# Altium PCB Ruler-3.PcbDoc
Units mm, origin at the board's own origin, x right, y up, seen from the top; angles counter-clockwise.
Board outline 100.08 x 35.05 mm, 2 copper layers (Top Layer, Bottom Layer); 12 components, 0 nets, 672 pads, 0 vias.
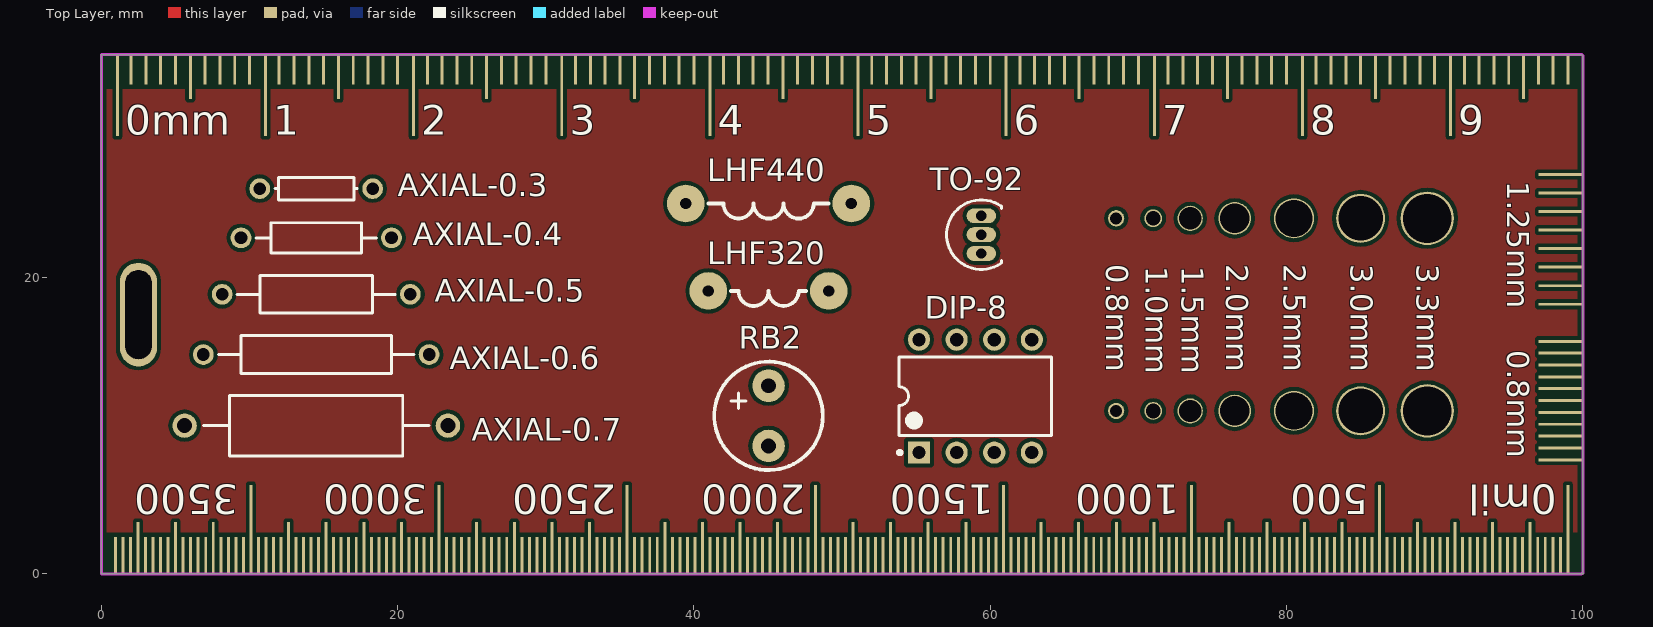
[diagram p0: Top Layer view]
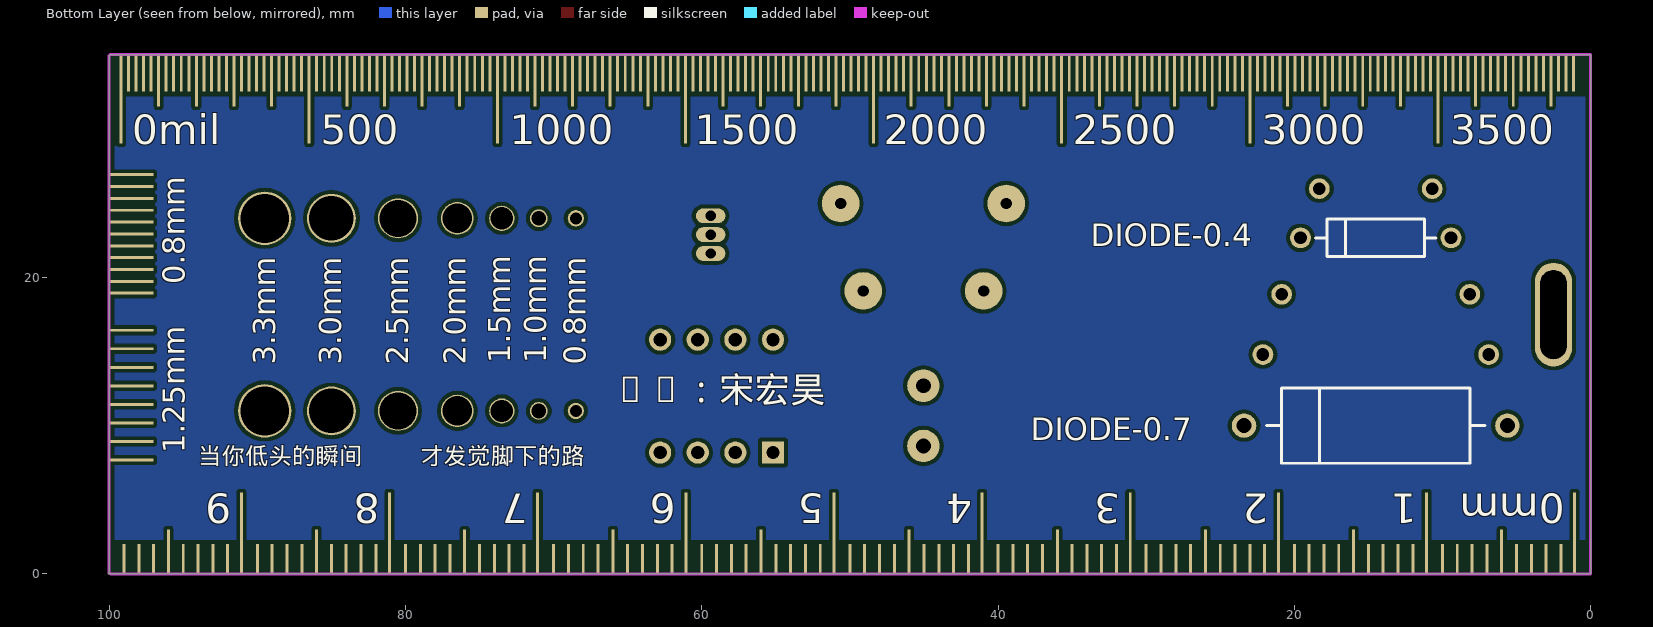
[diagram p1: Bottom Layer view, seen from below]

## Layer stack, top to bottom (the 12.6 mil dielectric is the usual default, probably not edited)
Top Solder: solder mask 0.0102, Solder Resist, Dk 3.5
Top Layer: signal copper 0.0356
Dielectric 1: dielectric 0.32, FR-4, Dk 4.8
Bottom Layer: signal copper 0.0356
Bottom Solder: solder mask 0.0102, Solder Resist, Dk 3.5

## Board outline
0,0 0,35.052 99.948,35.052 100,35 100,0.076 100.076,0

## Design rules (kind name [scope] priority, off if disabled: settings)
Clearance Clearance_1 [InPolygon] p1: gap=0.254 ignorepadtopadclearanceinfootprint=FALSE
Clearance [All] p2: gap=0.254 ignorepadtopadclearanceinfootprint=FALSE except(0: Arc-Hole Track-Hole SMDPad-Hole THPad-Hole Via-Hole Fill-Hole Poly-Hole Region-Hole Text-Hole)
PolygonConnect [All] p1: connectstyle=Relief reliefconductorwidth=0.254 reliefentries=4 polygonreliefangle="90 Angle" airgapwidth=0.254
RoutingVias [All] p1: holewidth=0.711 width=1.27 viastyle="Through Hole" minholewidth=0.711 minwidth=1.27 maxholewidth=0.711 maxwidth=1.27
SolderMaskExpansion [All] p1: expansion=0.102
Width [All] p1: maxlimit=0.254 minlimit=0.254 preferedwidth=0.254
30 further rules are at their usual default settings.

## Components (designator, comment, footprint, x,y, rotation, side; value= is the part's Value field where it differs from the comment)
AXIAL-0.3 "AXIAL-0.3" AXIAL-0.3 14.5,26 r0 top
AXIAL-0.4 "AXIAL-0.4" AXIAL-0.4 14.5,22.686 r0 top
AXIAL-0.5 "AXIAL-0.5" AXIAL-0.5 14.5,18.873 r0 top
AXIAL-0.6 "AXIAL-0.6" AXIAL-0.6 14.5,14.805 r0 top
AXIAL-0.7 "AXIAL-0.7" AXIAL-0.7 14.5,10 r0 top
DIODE-0.4 "DIODE-0.4" DIODE-0.4 14.503,22.682 r0 bottom
DIODE-0.7 "DIODE-0.7" DIODE-0.7 14.503,10.008 r0 bottom
DIP-8 "DIP-8" DIP-8 59,12 r90 top
LHF320 "LHF320" LHF320 49.1,19.1 r180 top
LHF440 "LHF440" LHF440 50.624,25 r180 top
RB2 "RB2" RB2 44.528,12.7 r90 top
TO-92 "TO-92" TO-92 59.399,22.9 r0 top

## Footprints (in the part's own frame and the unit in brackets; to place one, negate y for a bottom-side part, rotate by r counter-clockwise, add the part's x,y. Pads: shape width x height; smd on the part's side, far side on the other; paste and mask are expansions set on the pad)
AXIAL-0.3 [mm] "Axial Device, Thru-Hole; 2 Leads; 0.3 in Pin Spacing"
  round 1.4 hole 0.85: 1(-3.81,0) 2(3.81,0)
  silkscreen extent -2.77,-0.76 2.77,0.76
AXIAL-0.4 [mm] "Axial Device, Thru-Hole; 2 Leads; 0.4 in Pin Spacing"
  round 1.4 hole 0.85: 1(-5.08,0) 2(5.08,0)
  silkscreen extent -4.06,-1.02 4.06,1.02
AXIAL-0.5 [mm] "Axial Device, Thru-Hole; 2 Leads; 0.5 in Pin Spacing"
  round 1.4 hole 0.85: 1(-6.35,0) 2(6.35,0)
  silkscreen extent -5.33,-1.27 5.33,1.27
AXIAL-0.6 [mm] "Axial Device, Thru-Hole; 2 Leads; 0.6 in Pin Spacing"
  round 1.4 hole 0.85: 1(-7.62,0) 2(7.62,0)
  silkscreen extent -6.6,-1.27 6.6,1.27
AXIAL-0.7 [mm] "Axial Device, Thru-Hole; 2 Leads; 0.7 in Pin Spacing"
  round 1.4 hole 0.85: 1(-8.89,0) 2(8.89,0)
  silkscreen extent -7.62,-2.03 7.62,2.03
DIODE-0.4 [mm] "Diode, Thru-Hole; 2 Leads; 0.4 in Pin Spacing"
  round 1.4 hole 0.85: 1(-5.08,0) 2(5.08,0)
  silkscreen extent -4.06,-1.27 4.06,1.27
DIODE-0.7 [mm] "Diode, Thru-Hole; 2 Leads; 0.7 in Pin Spacing"
  round 1.65 hole 1: 1(-8.89,0) 2(8.89,0)
  silkscreen extent -7.37,-2.54 7.37,2.54
DIP-8 [mm] "DIP; 8 Leads; Row Spacing 7.62 mm; Pitch 2.54 mm"
  rect 1.5x1.5 hole 0.9: 1(-3.81,3.81)
  round 1.5 hole 0.9: 2(-3.81,1.27) 3(-3.81,-1.27) 4(-3.81,-3.81) 5(3.81,-3.81) 6(3.81,-1.27) 7(3.81,1.27) 8(3.81,3.81)
  silkscreen extent -3.93,-5.15 2.65,5.23, body extent -3.6,-5.15 3.6,5.15, height 5.08
LHF320 [mil]
  round 100 hole 30: 1(0,0) 2(320,0)
  silkscreen extent 60,0 260,40
LHF440 [mil]
  round 100 hole 30: 1(0,0) 2(440,0)
  silkscreen extent 60,0 380,40
RB2 [mm]
  round 2.2 hole 1: 1(0,-0.508) 2(-4.064,-0.508)
  silkscreen extent -5.69,-4.17 1.63,3.15
TO-92 [mm] "TO, Flat Index; 3 In-Line, Axial Leads; Body Dia. 4.6mm; Leads 0.41 x 0.39 mm (max)"
  oval 2x1 hole 0.7: 1(0,1.27) 2(0,0) 3(0,-1.27)
  silkscreen extent -2.34,-2.34 1.35,2.34

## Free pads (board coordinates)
  oval 2.5x7 hole 1.8 slot 6 at 90 deg: 0(2.5,17.5)
  rect 0.2x5.5 smd far side: 1(1.075,2.752) 11(11.075,2.752) 21(21.075,2.752) 31(31.075,2.752) 41(41.075,2.752) 51(51.075,2.752) 61(61.075,2.752) 71(71.075,2.752) 81(81.075,2.752) 91(91.075,2.752)
  rect 0.2x5.5 smd: 1(1.075,32.3) 11(11.075,32.3) 21(21.075,32.3) 31(31.075,32.3) 41(41.075,32.3) 51(51.075,32.3) 61(61.075,32.3) 71(71.075,32.3) 81(81.075,32.3) 91(91.075,32.3)
  round 3.3 hole 3: 1(85,24) 2(85,11)
  rect 0.2x2 smd far side: 2(2,1.002) 3(3,1.002) 4(4,1.002) 5(5,1.002) 7(7,1.002) 8(8,1.002) 9(9,1.002) 10(10,1.002) 12(12,1.002) 13(13,1.002) 14(14,1.002) 15(15,1.002) 17(17,1.002) 18(18,1.002) 19(19,1.002) 20(20,1.002) 22(22,1.002) 23(23,1.002) 24(24,1.002) 25(25,1.002) 27(27,1.002) 28(28,1.002) 29(29,1.002) 30(30,1.002) 32(32,1.002) 33(33,1.002) 34(34,1.002) 35(35,1.002) 37(37,1.002) 38(38,1.002) 39(39,1.002) 40(40,1.002) 42(42,1.002) 43(43,1.002) 44(44,1.002) 45(45,1.002) 47(47,1.002) 48(48,1.002) 49(49,1.002) 50(50,1.002) 52(52,1.002) 53(53,1.002) 54(54,1.002) 55(55,1.002) 57(57,1.002) 58(58,1.002) 59(59,1.002) 60(60,1.002) 62(62,1.002) 63(63,1.002) 64(64,1.002) 65(65,1.002) 67(67,1.002) 68(68,1.002) 69(69,1.002) 70(70,1.002) 72(72,1.002) 73(73,1.002) 74(74,1.002) 75(75,1.002) 77(77,1.002) 78(78,1.002) 79(79,1.002) 80(80,1.002) 82(82,1.002) 83(83,1.002) 84(84,1.002) 85(85,1.002) 87(87,1.002) 88(88,1.002) 89(89,1.002) 90(90,1.002) 92(92,1.002) 93(92,1.002) 94(93,1.002) 95(94,1.002) 96(95,1.002) 98(97,1.002) 99(98,1.002) 100(99,1.002)
  rect 0.2x2 smd: 2(2,34.05) 3(3,34.05) 4(4,34.05) 5(5,34.05) 7(7,34.05) 8(8,34.05) 9(9,34.05) 10(10,34.05) 12(12,34.05) 13(13,34.05) 14(14,34.05) 15(15,34.05) 17(17,34.05) 18(18,34.05) 19(19,34.05) 20(20,34.05) 22(22,34.05) 23(23,34.05) 24(24,34.05) 25(25,34.05) 27(27,34.05) 28(28,34.05) 29(29,34.05) 30(30,34.05) 32(32,34.05) 33(33,34.05) 34(34,34.05) 35(35,34.05) 37(37,34.05) 38(38,34.05) 39(39,34.05) 40(40,34.05) 42(42,34.05) 43(43,34.05) 44(44,34.05) 45(45,34.05) 47(47,34.05) 48(48,34.05) 49(49,34.05) 50(50,34.05) 52(52,34.05) 53(53,34.05) 54(54,34.05) 55(55,34.05) 57(57,34.05) 58(58,34.05) 59(59,34.05) 60(60,34.05) 62(62,34.05) 63(63,34.05) 64(64,34.05) 65(65,34.05) 67(67,34.05) 68(68,34.05) 69(69,34.05) 70(70,34.05) 72(72,34.05) 73(73,34.05) 74(74,34.05) 75(75,34.05) 77(77,34.05) 78(78,34.05) 79(79,34.05) 80(80,34.05) 82(82,34.05) 83(83,34.05) 84(84,34.05) 85(85,34.05) 87(87,34.05) 88(88,34.05) 89(89,34.05) 90(90,34.05) 92(92,34.05) 93(92,34.05) 94(93,34.05) 95(94,34.05) 96(95,34.05) 98(97,34.05) 99(98,34.05) 100(99,34.05)
  rect 0.2x3 smd far side: 6(6,1.502) 16(16,1.502) 26(26,1.502) 36(36,1.502) 46(46,1.502) 56(56,1.502) 66(66,1.502) 76(76,1.502) 86(86,1.502) 97(96,1.502)
  rect 0.2x3 smd: 6(6,33.55) 16(16,33.55) 26(26,33.55) 36(36,33.55) 46(46,33.55) 56(56,33.55) 66(66,33.55) 76(76,33.55) 86(86,33.55) 97(96,33.55)
  rect 0.2x6 smd: 102(98.99,3.002) 129(86.29,3.002) 154(73.59,3.002) 179(60.89,3.002) 204(48.19,3.002) 229(35.49,3.002) 254(22.79,3.002) 279(10.09,3.002)
  rect 0.2x6 smd far side: 102(99.2,32.05) 129(86.5,32.05) 154(73.8,32.05) 179(61.1,32.05) 204(48.4,32.05) 229(35.7,32.05) 254(23,32.05) 279(10.3,32.05)
  rect 0.2x2.5 smd: 103(98.482,1.252) 104(97.974,1.252) 107(97.466,1.252) 108(96.958,1.252) 110(95.942,1.252) 111(95.434,1.252) 112(94.926,1.252) 113(94.418,1.252) 115(93.402,1.252) 116(92.894,1.252) 117(92.386,1.252) 118(91.878,1.252) 120(90.862,1.252) 121(90.354,1.252) 122(89.846,1.252) 123(89.338,1.252) 125(88.322,1.252) 126(87.814,1.252) 127(87.306,1.252) 128(86.798,1.252) 130(85.782,1.252) 131(85.274,1.252) 132(84.766,1.252) 133(84.258,1.252) 135(83.242,1.252) 136(82.734,1.252) 137(82.226,1.252) 138(81.718,1.252) 140(80.702,1.252) 141(80.194,1.252) 142(79.686,1.252) 143(79.178,1.252) 145(78.162,1.252) 146(77.654,1.252) 147(77.146,1.252) 148(76.638,1.252) 150(75.622,1.252) 151(75.114,1.252) 152(74.606,1.252) 153(74.098,1.252) 155(73.082,1.252) 156(72.574,1.252) 157(72.066,1.252) 158(71.558,1.252) 160(70.542,1.252) 161(70.034,1.252) 162(69.526,1.252) 163(69.018,1.252) 165(68.002,1.252) 166(67.494,1.252) 167(66.986,1.252) 168(66.478,1.252) 170(65.462,1.252) 171(64.954,1.252) 172(64.446,1.252) 173(63.938,1.252) 175(62.922,1.252) 176(62.414,1.252) 177(61.906,1.252) 178(61.398,1.252) 180(60.382,1.252) 181(59.874,1.252) 182(59.366,1.252) 183(58.858,1.252) 185(57.842,1.252) 186(57.334,1.252) 187(56.826,1.252) 188(56.318,1.252) 190(55.302,1.252) 191(54.794,1.252) 192(54.286,1.252) 193(53.778,1.252) 195(52.762,1.252) 196(52.254,1.252) 197(51.746,1.252) 198(51.238,1.252) 200(50.222,1.252) 201(49.714,1.252) 202(49.206,1.252) 203(48.698,1.252) 205(47.682,1.252) 206(47.174,1.252) 207(46.666,1.252) 208(46.158,1.252) 210(45.142,1.252) 211(44.634,1.252) 212(44.126,1.252) 213(43.618,1.252) 215(42.602,1.252) 216(42.094,1.252) 217(41.586,1.252) 218(41.078,1.252) 220(40.062,1.252) 221(39.554,1.252) 222(39.046,1.252) 223(38.538,1.252) 225(37.522,1.252) 226(37.014,1.252) 227(36.506,1.252) 228(35.998,1.252) 230(34.982,1.252) 231(34.474,1.252) 232(33.966,1.252) 233(33.458,1.252) 235(32.442,1.252) 236(31.934,1.252) 237(31.426,1.252) 238(30.918,1.252) 240(29.902,1.252) 241(29.394,1.252) 242(28.886,1.252) 243(28.378,1.252) 245(27.362,1.252) 246(26.854,1.252) 247(26.346,1.252) 248(25.838,1.252) 250(24.822,1.252) 251(24.314,1.252) 252(23.806,1.252) 253(23.298,1.252) 255(22.282,1.252) 256(21.774,1.252) 257(21.266,1.252) 258(20.758,1.252) 260(19.742,1.252) 261(19.234,1.252) 262(18.726,1.252) 263(18.218,1.252) 265(17.202,1.252) 266(16.694,1.252) 267(16.186,1.252) 268(15.678,1.252) 270(14.662,1.252) 271(14.154,1.252) 272(13.646,1.252) 273(13.138,1.252) 275(12.122,1.252) 276(11.614,1.252) 277(11.106,1.252) 278(10.598,1.252) 280(9.582,1.252) 281(9.074,1.252) 282(8.566,1.252) 283(8.058,1.252) 285(7.042,1.252) 286(6.534,1.252) 287(6.026,1.252) 288(5.518,1.252) 290(4.502,1.252) 291(3.994,1.252) 292(3.486,1.252) 293(2.978,1.252) 295(1.962,1.252) 296(1.454,1.252) 297(0.946,1.252)
  rect 0.2x2.5 smd far side: 103(98.692,33.8) 104(98.184,33.8) 107(97.676,33.8) 108(97.168,33.8) 110(96.152,33.8) 111(95.644,33.8) 112(95.136,33.8) 113(94.628,33.8) 115(93.612,33.8) 116(93.104,33.8) 117(92.596,33.8) 118(92.088,33.8) 120(91.072,33.8) 121(90.564,33.8) 122(90.056,33.8) 123(89.548,33.8) 125(88.532,33.8) 126(88.024,33.8) 127(87.516,33.8) 128(87.008,33.8) 130(85.992,33.8) 131(85.484,33.8) 132(84.976,33.8) 133(84.468,33.8) 135(83.452,33.8) 136(82.944,33.8) 137(82.436,33.8) 138(81.928,33.8) 140(80.912,33.8) 141(80.404,33.8) 142(79.896,33.8) 143(79.388,33.8) 145(78.372,33.8) 146(77.864,33.8) 147(77.356,33.8) 148(76.848,33.8) 150(75.832,33.8) 151(75.324,33.8) 152(74.816,33.8) 153(74.308,33.8) 155(73.292,33.8) 156(72.784,33.8) 157(72.276,33.8) 158(71.768,33.8) 160(70.752,33.8) 161(70.244,33.8) 162(69.736,33.8) 163(69.228,33.8) 165(68.212,33.8) 166(67.704,33.8) 167(67.196,33.8) 168(66.688,33.8) 170(65.672,33.8) 171(65.164,33.8) 172(64.656,33.8) 173(64.148,33.8) 175(63.132,33.8) 176(62.624,33.8) 177(62.116,33.8) 178(61.608,33.8) 180(60.592,33.8) 181(60.084,33.8) 182(59.576,33.8) 183(59.068,33.8) 185(58.052,33.8) 186(57.544,33.8) 187(57.036,33.8) 188(56.528,33.8) 190(55.512,33.8) 191(55.004,33.8) 192(54.496,33.8) 193(53.988,33.8) 195(52.972,33.8) 196(52.464,33.8) 197(51.956,33.8) 198(51.448,33.8) 200(50.432,33.8) 201(49.924,33.8) 202(49.416,33.8) 203(48.908,33.8) 205(47.892,33.8) 206(47.384,33.8) 207(46.876,33.8) 208(46.368,33.8) 210(45.352,33.8) 211(44.844,33.8) 212(44.336,33.8) 213(43.828,33.8) 215(42.812,33.8) 216(42.304,33.8) 217(41.796,33.8) 218(41.288,33.8) 220(40.272,33.8) 221(39.764,33.8) 222(39.256,33.8) 223(38.748,33.8) 225(37.732,33.8) 226(37.224,33.8) 227(36.716,33.8) 228(36.208,33.8) 230(35.192,33.8) 231(34.684,33.8) 232(34.176,33.8) 233(33.668,33.8) 235(32.652,33.8) 236(32.144,33.8) 237(31.636,33.8) 238(31.128,33.8) 240(30.112,33.8) 241(29.604,33.8) 242(29.096,33.8) 243(28.588,33.8) 245(27.572,33.8) 246(27.064,33.8) 247(26.556,33.8) 248(26.048,33.8) 250(25.032,33.8) 251(24.524,33.8) 252(24.016,33.8) 253(23.508,33.8) 255(22.492,33.8) 256(21.984,33.8) 257(21.476,33.8) 258(20.968,33.8) 260(19.952,33.8) 261(19.444,33.8) 262(18.936,33.8) 263(18.428,33.8) 265(17.412,33.8) 266(16.904,33.8) 267(16.396,33.8) 268(15.888,33.8) 270(14.872,33.8) 271(14.364,33.8) 272(13.856,33.8) 273(13.348,33.8) 275(12.332,33.8) 276(11.824,33.8) 277(11.316,33.8) 278(10.808,33.8) 280(9.792,33.8) 281(9.284,33.8) 282(8.776,33.8) 283(8.268,33.8) 285(7.252,33.8) 286(6.744,33.8) 287(6.236,33.8) 288(5.728,33.8) 290(4.712,33.8) 291(4.204,33.8) 292(3.696,33.8) 293(3.188,33.8) 295(2.172,33.8) 296(1.664,33.8) 297(1.156,33.8)
  rect 0.2x3.5 smd: 109(96.45,1.752) 114(93.91,1.752) 119(91.37,1.752) 124(88.83,1.752) 134(83.75,1.752) 139(81.21,1.752) 144(78.67,1.752) 149(76.13,1.752) 159(71.05,1.752) 164(68.51,1.752) 169(65.97,1.752) 174(63.43,1.752) 184(58.35,1.752) 189(55.81,1.752) 194(53.27,1.752) 199(50.73,1.752) 209(45.65,1.752) 214(43.11,1.752) 219(40.57,1.752) 224(38.03,1.752) 234(32.95,1.752) 239(30.41,1.752) 244(27.87,1.752) 249(25.33,1.752) 259(20.25,1.752) 264(17.71,1.752) 269(15.17,1.752) 274(12.63,1.752) 284(7.55,1.752) 289(5.01,1.752) 294(2.47,1.752)
  rect 0.2x3.5 smd far side: 109(96.66,33.3) 114(94.12,33.3) 119(91.58,33.3) 124(89.04,33.3) 134(83.96,33.3) 139(81.42,33.3) 144(78.88,33.3) 149(76.34,33.3) 159(71.26,33.3) 164(68.72,33.3) 169(66.18,33.3) 174(63.64,33.3) 184(58.56,33.3) 189(56.02,33.3) 194(53.48,33.3) 199(50.94,33.3) 209(45.86,33.3) 214(43.32,33.3) 219(40.78,33.3) 224(38.24,33.3) 234(33.16,33.3) 239(30.62,33.3) 244(28.08,33.3) 249(25.54,33.3) 259(20.46,33.3) 264(17.92,33.3) 269(15.38,33.3) 274(12.84,33.3) 284(7.76,33.3) 289(5.22,33.3) 294(2.68,33.3)
  rect 3x0.2 smd far side: 125(98.498,7.696) 125(98.498,8.946) 125(98.498,10.196) 125(98.498,11.446) 125(98.498,12.696) 125(98.498,13.946) 125(98.498,15.196) 125(98.498,16.446) 125(98.498,18.946) 125(98.498,19.746) 125(98.498,20.546) 125(98.498,21.346) 125(98.498,22.146) 125(98.498,22.946) 125(98.498,23.746) 125(98.498,24.546) 125(98.498,25.346) 125(98.498,26.146) 125(98.498,26.946)
  rect 3x0.2 smd: 125(98.498,7.7) 125(98.498,8.5) 125(98.498,9.3) 125(98.498,10.1) 125(98.498,10.9) 125(98.498,11.7) 125(98.498,12.5) 125(98.498,13.3) 125(98.498,14.1) 125(98.498,14.9) 125(98.498,15.7) 125(98.498,18.2) 125(98.498,19.45) 125(98.498,20.7) 125(98.498,21.95) 125(98.498,23.2) 125(98.498,24.45) 125(98.498,25.7) 125(98.498,26.95)
  round 3.6 hole 3.3: 298(89.5,24) 299(89.5,11)
  round 2.7 hole 2.5: 302(80.5,24) 303(80.5,11)
  round 2.2 hole 2: 304(76.5,24) 305(76.5,11)
  round 1.7 hole 1.5: 306(73.5,24) 307(73.5,11)
  round 1.2 hole 1: 308(71,24) 309(71,11)
  round 1.1 hole 0.8: 310(68.5,24) 311(68.5,11)

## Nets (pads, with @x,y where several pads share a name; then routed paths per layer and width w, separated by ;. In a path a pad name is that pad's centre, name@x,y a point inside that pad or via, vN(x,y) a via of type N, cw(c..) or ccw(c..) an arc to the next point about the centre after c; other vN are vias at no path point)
pads on no net: AXIAL-0.3.1 AXIAL-0.3.2 AXIAL-0.4.1 AXIAL-0.4.2 AXIAL-0.5.1 AXIAL-0.5.2 AXIAL-0.6.1 AXIAL-0.6.2 AXIAL-0.7.1 AXIAL-0.7.2 DIODE-0.4.1 DIODE-0.4.2 DIODE-0.7.1 DIODE-0.7.2 DIP-8.1 DIP-8.2 DIP-8.3 DIP-8.4 DIP-8.5 DIP-8.6 DIP-8.7 DIP-8.8 LHF320.1 LHF320.2 LHF440.1 LHF440.2 RB2.1 RB2.2 TO-92.1 TO-92.2 TO-92.3

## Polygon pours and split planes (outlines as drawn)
no net on Top Layer "Top Layer-No Net" (solid, pour order 0): 0,32.7 100,32.7 100,2.8 0,2.8
no net on Bottom Layer "Top Layer-No Net" (solid, pour order 2): 0,32.2 100,32.2 100,2.3 0,2.3

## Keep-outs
Keep-Out Layer:
  lines w0.2: 0,0 0,35.052 99.948,35.052 100,35 100,0.076 99.924,0 0,0

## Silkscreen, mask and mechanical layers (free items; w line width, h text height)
Top Overlay:
  text "0mm" at 1.6,29.65 h2
  text "1" at 11.6,29.65 h2
  text "2" at 21.6,29.65 h2
  text "3" at 31.6,29.65 h2
  text "4" at 41.6,29.65 h2
  text "5" at 51.6,29.65 h2
  text "6" at 61.6,29.65 h2
  text "7" at 71.6,29.65 h2
  text "8" at 81.6,29.65 h2
  text "9" at 91.6,29.65 h2
  text "1.25mm" at 94.9,26.5 h1.5 r270
  text "0.8mm" at 67.843,20.9 h1.5 r270
  text "2.0mm" at 75.925,20.9 h1.5 r270
  text "2.5mm" at 79.825,20.9 h1.5 r270
  text "3.0mm" at 84.325,20.9 h1.5 r270
  text "3.3mm" at 88.798,20.9 h1.5 r270
  text "1.0mm" at 70.51,20.775 h1.5 r270
  text "1.5mm" at 72.923,20.775 h1.5 r270
  text "0.8mm" at 94.9,15.1 h1.5 r270
  text "3500" at 9.25,6 h2 r180
  text "3000" at 22,6 h2 r180
  text "2500" at 34.75,6 h2 r180
  text "2000" at 47.5,6 h2 r180
  text "1500" at 60.25,6 h2 r180
  text "1000" at 72.75,6 h2 r180
  text "500" at 85.5,6 h2 r180
  text "0mil" at 98.25,6 h2 r180
Bottom Overlay:
  text "3500" at 9.46,29.002 h2
  text "3000" at 22.21,29.002 h2
  text "2500" at 34.96,29.002 h2
  text "2000" at 47.71,29.002 h2
  text "1500" at 60.46,29.002 h2
  text "1000" at 72.96,29.002 h2
  text "500" at 85.71,29.002 h2
  text "0mil" at 98.46,29.002 h2
  text "0.8mm" at 94.9,19.546 h1.5 r270
  text "1.0mm" at 70.51,14.225 h1.5 r270
  text "1.5mm" at 72.923,14.225 h1.5 r270
  text "0.8mm" at 67.843,14.1 h1.5 r270
  text "2.0mm" at 75.925,14.1 h1.5 r270
  text "2.5mm" at 79.825,14.1 h1.5 r270
  text "3.0mm" at 84.325,14.1 h1.5 r270
  text "3.3mm" at 88.798,14.1 h1.5 r270
  text "By：宋宏昊" at 66,11 h3
  text "1.25mm" at 94.9,8.146 h1.5 r270
  text "才发觉脚下的路" at 79,7 h2
  text "当你低头的瞬间" at 94,7 h2
  text "0mm" at 1.75,5.4 h2 r180
  text "1" at 11.75,5.4 h2 r180
  text "2" at 21.75,5.4 h2 r180
  text "3" at 31.75,5.4 h2 r180
  text "4" at 41.75,5.4 h2 r180
  text "5" at 51.75,5.4 h2 r180
  text "6" at 61.75,5.4 h2 r180
  text "7" at 71.75,5.4 h2 r180
  text "8" at 81.75,5.4 h2 r180
  text "9" at 91.75,5.4 h2 r180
